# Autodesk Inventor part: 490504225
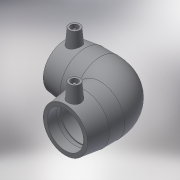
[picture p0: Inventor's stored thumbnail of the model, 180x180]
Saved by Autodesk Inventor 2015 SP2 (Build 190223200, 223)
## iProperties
Created: 2017-06
Part Number: 490504225
Material: Generic
Description: PLASSON 90° ELBOW 225
Document SubType Name: Modeling
Designer: KIM
Mass: 55.0731 g
Surface Area: 148.067 cm^2
Volume: 55.0731 cm^3
Density: 1 g/cm^3
Appearance: Default
Author: KIM
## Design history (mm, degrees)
derived "490504.ipt"
feature "Solid1::490504.ipt"
tag "TaggingFeature1"
body "Solid1"
other parameters: "d2" = 295, "d4" = 124.5, "d5" = 265.5, "d8" = 168 deg, "d10" = 48.4, "d11" = 16.13333, "d14" = 17.6296, "d18" = 225, "d19" = 3.52592, "d20" = 168 deg, "d22" = 271.4, "d23" = 295, "d24" = 263.258, "d30" = 15, "d31" = 174.3, "d34" = 5 deg, "d35" = 15, "d39" = 5 deg, "d41" = 4, "d42" = 14, "d43" = 0, "d45" = 4, "d46" = 14, "d47" = 0, "d49" = 225, "d50" = 191.25, "d51" = 48.4, "d52" = 121, "d54" = 90 deg, "d65" = 225, "d67" = 45 deg, "d71" = 90 deg, "d75" = 14.75, "d82" = 45 deg, "d83" = 121, "d84" = 265.5, "d86" = 132.75, "d87" = 90 deg, "d90" = 121, "d91" = 0, "d92" = 121, "d93" = 0, "d94" = 90 deg, "d95" = 135.7, "d98" = 498, "d101" = 3, "d102" = 0, "d103" = 3, "d104" = 0, "d105" = 35.09, "d106" = 8.7725, "d107" = 498, "d110" = 66.55, "d_" = 225, "L_" = 498, "L_1" = 121, "D_" = 295, "d_2" = 12
